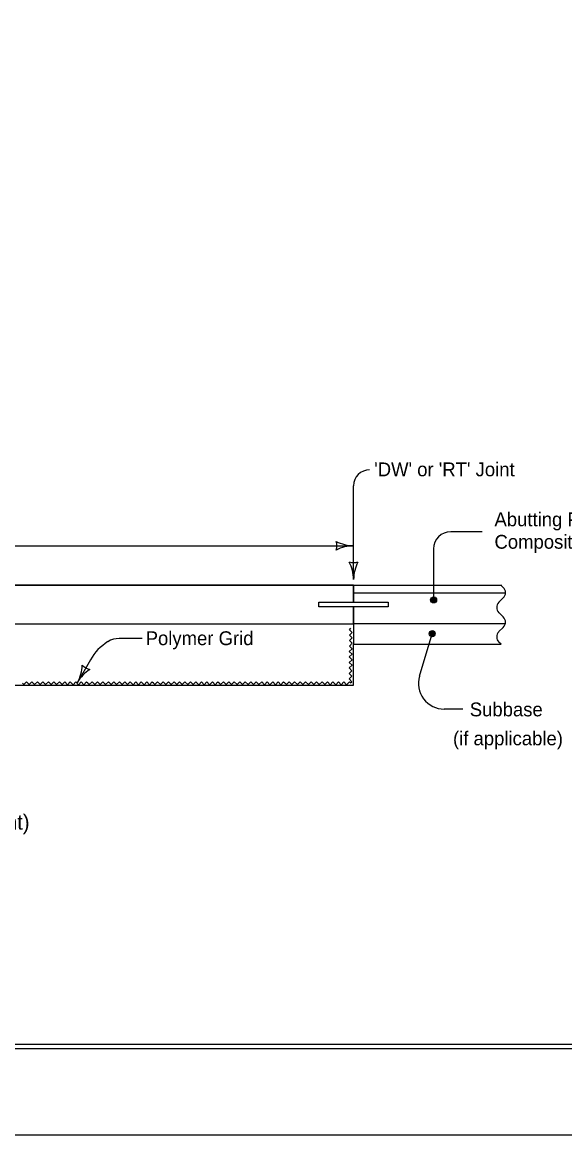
# Model space of a CAD drawing. Extents: x 10028 to 81668, y 6395 to 11634.
# Drawn here: x 22426 to 23054, y 7825 to 9112 of the extents above; entities that cross this region are included whole.
import ezdxf

# ---------------------------------------------------------------- set-up
doc = ezdxf.new("R2010")
doc.units = 0
for name, color, linetype in [('Default', 7, 'Continuous'), ('dsnCellElements', 7, 'Continuous'), ('dsnstdblockInterim', 7, 'Continuous'), ('dsnStdDimension', 7, 'Continuous'), ('ShtPlotIdentification', 7, 'Continuous')]:
    doc.layers.add(name, color=color, linetype=linetype)

msp = doc.modelspace()

# ---------------------------------------------------------------- linework, layer by layer
at = {"layer": 'Default'}
msp.add_lwpolyline([(20932.5, 9944), (24067.5, 9944), (24067.5, 7924), (20932.5, 7924)], close=True, dxfattribs=at)
at = {"layer": 'dsnstdblockInterim'}
msp.add_lwpolyline([(20932.5, 9939), (24067.5, 9939), (24067.5, 7929), (20932.5, 7929)], close=True, dxfattribs=at)
at = {"layer": 'dsnStdDimension'}
msp.add_lwpolyline([(20828, 7824.5), (24172, 7824.5), (24172, 10408.5), (20828, 10408.5)], close=True, dxfattribs=at)
at = {"layer": 'ShtPlotIdentification'}
for p, q in [((22809.5, 8467.2), (22809.5, 8575.4)), ((22958.5, 8522.4), (22922, 8522.4)), ((21882.9, 8506.2), (22809.5, 8506.2)), ((22902.2, 8502.6), (22902.2, 8443.4)), ((22809.5, 8460.4), (21893.1, 8460.4)), ((21893.1, 8460.4), (22809.5, 8460.4)), ((22809.5, 8440.9), (22809.5, 8460.4)), ((22809.5, 8460.4), (22809.5, 8440.9)), ((22809.5, 8460.4), (22981.3, 8460.4)), ((22982.8, 8457.8), (22980.3, 8460.3)), ((22809.5, 8451.6), (22985.3, 8451.6)), ((22977.8, 8440.8), (22982.8, 8445.8)), ((22769.4, 8435.4), (22769.4, 8440.9)), ((22769.4, 8440.9), (22809.5, 8440.9)), ((22769.4, 8435.4), (22769.4, 8440.9)), ((22769.4, 8440.9), (22849.6, 8440.9)), ((22809.5, 8435.4), (22769.4, 8435.4)), ((22849.6, 8435.4), (22769.4, 8435.4)), ((22809.5, 8415.9), (22809.5, 8435.4)), ((22809.5, 8435.4), (22809.5, 8415.9)), ((22849.6, 8440.9), (22849.6, 8435.4)), ((22980.3, 8426.2), (22977.8, 8428.7)), ((22982.8, 8423.7), (22980.3, 8426.2)), ((21934.1, 8415.9), (22809.5, 8415.9)), ((21934.1, 8415.9), (22809.5, 8415.9)), ((22809.5, 8415.9), (22809.5, 8392.1)), ((22984.3, 8415.9), (22809.5, 8415.9)), ((22977.8, 8406.7), (22982.8, 8411.7)), ((22565, 8398.8), (22538.4, 8398.8)), ((22885.9, 8355.3), (22900.5, 8404.3)), ((22980.3, 8392.1), (22977.8, 8394.6)), ((22809.5, 8379.7), (22809.5, 8392.1)), ((22809.5, 8392.1), (22980.3, 8392.1)), ((22504.9, 8374.1), (22489.9, 8348)), ((22809.5, 8344.6), (22809.5, 8379.7)), ((21912.6, 8344.6), (22809.5, 8344.6)), ((22936.1, 8317.1), (22914.4, 8317.1))]:
    msp.add_line(p, q, dxfattribs=at)
for points in [[(22905.4, 8443.1), (22904.9, 8444.3), (22904.3, 8446.1), (22902.5, 8446.4), (22900.9, 8446.2), (22899.4, 8445), (22899.5, 8443.3), (22899.8, 8441.5), (22901.2, 8440.6), (22902.8, 8440.4), (22904.8, 8441.5), (22904.9, 8442.8), (22904.5, 8444.7), (22903.3, 8446.1), (22901.6, 8446.1), (22900.2, 8444.9), (22900, 8443.3), (22900.4, 8441.5), (22901.4, 8441.2), (22902.7, 8440.8), (22904.2, 8441.7), (22904.1, 8443), (22903.9, 8444.5), (22903, 8445.6), (22901.5, 8445.1), (22900.6, 8443.9), (22900.6, 8442.4), (22901.4, 8442), (22902.3, 8441.5), (22903.5, 8442.3), (22903.8, 8443.4), (22903.3, 8444.4), (22902.1, 8444.5), (22901.3, 8444), (22901.1, 8442.9), (22901.5, 8442.4), (22902.1, 8442.1), (22903, 8442.7), (22903.2, 8443.4), (22902.8, 8444.1), (22902.2, 8444), (22901.8, 8443.5), (22901.8, 8442.7), (22902.3, 8442.8), (22902.6, 8443.4)], [(22806.1, 8347.3), (22807.7, 8348.8), (22804.5, 8352), (22807.7, 8355.2), (22804.6, 8358.4), (22807.7, 8361.5), (22804.6, 8364.7), (22807.8, 8367.8), (22804.6, 8371), (22807.8, 8374.2), (22804.6, 8377.4), (22807.8, 8380.5), (22804.6, 8383.7), (22807.8, 8386.8), (22804.7, 8390), (22807.8, 8393.2), (22804.7, 8396.4), (22807.8, 8399.5), (22804.7, 8402.7), (22807.9, 8405.9), (22804.7, 8409), (22806.3, 8410.7)], [(22900.7, 8407.5), (22899.6, 8406.9), (22897.8, 8406.4), (22897.4, 8404.5), (22897.7, 8402.9), (22898.8, 8401.4), (22900.5, 8401.6), (22902.4, 8401.8), (22903.2, 8403.3), (22903.4, 8404.8), (22902.3, 8406.8), (22901, 8407), (22899.2, 8406.5), (22897.7, 8405.4), (22897.7, 8403.6), (22898.9, 8402.2), (22900.5, 8402.1), (22902.4, 8402.4), (22902.6, 8403.5), (22903, 8404.7), (22902.1, 8406.2), (22900.8, 8406.2), (22899.3, 8405.9), (22898.2, 8405.1), (22898.8, 8403.5), (22899.9, 8402.7), (22901.4, 8402.6), (22901.8, 8403.4), (22902.3, 8404.4), (22901.6, 8405.6), (22900.4, 8405.8), (22899.4, 8405.3), (22899.4, 8404.2), (22899.9, 8403.4), (22900.9, 8403.1), (22901.4, 8403.5), (22901.7, 8404.1), (22901.2, 8405), (22900.4, 8405.2), (22899.7, 8404.8), (22899.9, 8404.2), (22900.4, 8403.8), (22901.1, 8403.8), (22901.1, 8404.3), (22900.5, 8404.6)], [(22426.2, 8347.1), (22427.8, 8345.5), (22430.9, 8348.6), (22434.1, 8345.5), (22437.3, 8348.6), (22440.4, 8345.4), (22443.6, 8348.6), (22446.8, 8345.4), (22450, 8348.6), (22453.1, 8345.4), (22456.3, 8348.6), (22459.4, 8345.4), (22462.6, 8348.6), (22465.8, 8345.4), (22469, 8348.5), (22472.1, 8345.4), (22475.3, 8348.5), (22478.4, 8345.3), (22481.6, 8348.5), (22484.8, 8345.3), (22488, 8348.5), (22491.1, 8345.3), (22494.3, 8348.5), (22497.5, 8345.3), (22500.6, 8348.5), (22502.1, 8347.3)], [(22502, 8347.1), (22503.6, 8345.5), (22506.8, 8348.6), (22510, 8345.5), (22513.1, 8348.6), (22516.3, 8345.4), (22519.5, 8348.6), (22522.6, 8345.4), (22525.8, 8348.6), (22529, 8345.4), (22532.1, 8348.6), (22535.3, 8345.4), (22538.5, 8348.6), (22541.6, 8345.4), (22544.8, 8348.5), (22548, 8345.4), (22551.1, 8348.5), (22554.3, 8345.3), (22557.5, 8348.5), (22560.6, 8345.3), (22563.8, 8348.5), (22567, 8345.3), (22570.2, 8348.5), (22573.3, 8345.3), (22576.5, 8348.5), (22577.9, 8347.3)], [(22578, 8347.1), (22579.6, 8345.5), (22582.7, 8348.6), (22585.9, 8345.5), (22589.1, 8348.6), (22592.2, 8345.4), (22595.4, 8348.6), (22598.6, 8345.4), (22601.8, 8348.6), (22604.9, 8345.4), (22608.1, 8348.6), (22611.3, 8345.4), (22614.4, 8348.6), (22617.6, 8345.4), (22620.8, 8348.5), (22623.9, 8345.4), (22627.1, 8348.5), (22630.3, 8345.3), (22633.4, 8348.5), (22636.6, 8345.3), (22639.8, 8348.5), (22642.9, 8345.3), (22646.1, 8348.5), (22649.3, 8345.3), (22652.4, 8348.5), (22653.9, 8347.3)], [(22654.1, 8347.1), (22655.7, 8345.5), (22658.9, 8348.6), (22662, 8345.5), (22665.2, 8348.6), (22668.4, 8345.4), (22671.5, 8348.6), (22674.7, 8345.4), (22677.9, 8348.6), (22681, 8345.4), (22684.2, 8348.6), (22687.4, 8345.4), (22690.6, 8348.6), (22693.7, 8345.4), (22696.9, 8348.5), (22700, 8345.4), (22703.2, 8348.5), (22706.4, 8345.3), (22709.6, 8348.5), (22712.7, 8345.3), (22715.9, 8348.5), (22719, 8345.3), (22722.2, 8348.5), (22725.4, 8345.3), (22728.6, 8348.5), (22730, 8347.3)], [(22730.3, 8347.1), (22731.8, 8345.5), (22735, 8348.6), (22738.2, 8345.5), (22741.3, 8348.6), (22744.5, 8345.4), (22747.7, 8348.6), (22750.8, 8345.4), (22754, 8348.6), (22757.2, 8345.4), (22760.4, 8348.6), (22763.5, 8345.4), (22766.7, 8348.6), (22769.8, 8345.4), (22773, 8348.5), (22776.2, 8345.4), (22779.4, 8348.5), (22782.5, 8345.3), (22785.7, 8348.5), (22788.9, 8345.3), (22792, 8348.5), (22795.2, 8345.3), (22798.4, 8348.5), (22801.5, 8345.3), (22804.7, 8348.5), (22806.1, 8347.3)]]:
    msp.add_lwpolyline(points, dxfattribs=at)
for centre in [(22902.2, 8443.4), (22900.5, 8404.3)]:
    msp.add_circle(centre, 3.47, dxfattribs=at)
for centre, radius, start, end in [((22828.1, 8575.4), 18.6, 90, 180), ((22773.7, 8506.2), 16.5, 342.2666, 17.7333), ((22809.5, 8548.9), 42.7, 241.9275, 270), ((22773.7, 8506.2), 16.5, 342.2666, 17.7333), ((22809.5, 8548.9), 42.7, 241.9275, 270), ((22922, 8502.6), 19.8, 90, 180), ((22809.5, 8463.4), 42.7, 90, 118.0725), ((22809.5, 8463.4), 42.7, 90, 118.0725), ((22809.5, 8503.1), 16.5, 252.2666, 287.7333), ((22766.8, 8467.2), 42.7, 360, 28.0725), ((22809.5, 8503.1), 16.5, 252.2666, 287.7333), ((22766.8, 8467.2), 42.7, 360, 28.0725), ((22852.3, 8467.2), 42.7, 151.9275, 180), ((22852.3, 8467.2), 42.7, 151.9275, 180), ((22976.8, 8451.8), 8.53, 315, 45), ((22983.8, 8434.7), 8.53, 135, 225), ((22976.8, 8417.7), 8.53, 315, 45), ((22556.4, 8344.6), 59.4, 121.7183, 150.1783), ((22538.4, 8373.8), 25, 90, 121.7183), ((22983.8, 8400.6), 8.53, 135, 225), ((22452.8, 8369.2), 42.7, 330.1795, 358.2519), ((22527, 8326.7), 42.7, 122.107, 150.1794), ((22507.7, 8379.1), 16.5, 222.4461, 257.9128), ((22914.4, 8346.8), 29.7, 163.4172, 270)]:
    msp.add_arc(centre, radius, start, end, dxfattribs=at)

# ---------------------------------------------------------------- texts
at = {"layer": 'dsnCellElements'}
for s, height, p in [("'DW' or 'RT' Joint", 16, (22833.4, 8586.5)), ('Abutting PCC or', 16, (22972.6, 8528.7)), ('Composite Pavement', 16, (22972.6, 8502.7)), ('Polymer Grid', 16, (22568.9, 8391.1)), ('Subbase', 16, (22944, 8308.7)), ('(if applicable)', 16, (22924.6, 8275.2)), ('(Doweled PCC Pavement)', 17.5, (22160.1, 8177.6))]:
    msp.add_text(s, height=height, dxfattribs=at).set_placement(p)

doc.saveas('drawing.dxf')
